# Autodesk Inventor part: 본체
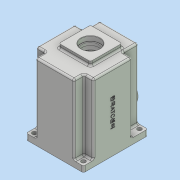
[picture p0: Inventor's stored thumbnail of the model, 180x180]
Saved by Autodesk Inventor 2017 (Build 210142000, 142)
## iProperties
Part Number: 본체
Material: 일반
Document SubType Name: Modeling
Designer: MRC
Density: 1 g/cm^3
Appearance: 기본값
Author: MRC
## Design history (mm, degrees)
sketch "스케치1"
  geometry: L1 (-33, -55)-(33, -55); L2 (33, -55)-(33, 55); L3 (33, 55)-(-33, 55); L4 (-33, 55)-(-33, -55); L5 (-33, -55)-(33, 55); L6 (33, -55)-(-33, 55); 1 further point
  constraints: 12 end point, 2 midpoint, 2 parallel, 1 horizontal, 1 perpendicular
  dimensions: "d0" = 66 distance of L3.end L2.end; "d1" = 110 distance of L2.end L1.end
extrude "돌출1" new body sketch "스케치1" distance "d2" = 130; taper "d3" = 0 deg
sketch "스케치2"
  geometry: L1 (-49, -38)-(49, -38); L2 (49, -38)-(49, 28); L3 (49, 28)-(-49, 28); L4 (-49, 28)-(-49, -38); L5 (-49, -38)-(49, 28); L6 (49, -38)-(-49, 28); L7 (-33, -55)-(33, -55) reference; 3 further points
  constraints: 12 end point, 3 midpoint, 2 parallel, 1 horizontal, 1 perpendicular, 1 vertical alignment
  dimensions: "d4" = 98 distance of L2.end L3.end; "d5" = 66 distance of L1.end L2.end; "d6" = 17 distance between parallel lines of L1 L7
extrude "돌출2" join sketch "스케치2" distance "d7" = 130; taper "d8" = 0 deg
sketch "스케치3"
  geometry: L1 (-49, -55)-(49, -55); L2 (49, -55)-(49, 55); L3 (49, 55)-(-49, 55); L4 (-49, 55)-(-49, -55); L5 (-49, -55)-(49, 55); L6 (49, -55)-(-49, 55); L7 (33, -55)-(-33, -55) reference; 3 further points
  constraints: 12 end point, 4 midpoint, 2 parallel, 1 horizontal, 1 perpendicular
  dimensions: "d9" = 98 distance of L3.end L2.end; "d10" = 110 distance of L2.end L1.end
extrude "돌출3" join sketch "스케치3" distance "d11" = 10; taper "d12" = 0 deg
node "작업 평면1"
sketch "스케치7"
  geometry: L1 (49, -55)-(-49, -55) reference; L2 (-26, 48)-(26, 48); L3 (-26, 48)-(-26, 31.729); L4 (26, 48)-(26, 31.729); A1 r 45 centre (0, -5) between (-26, 31.729) and (26, 31.729); 2 further points
  constraints: 6 end point, 2 point on circle, 2 vertical, 2 vertical alignment, 1 centre point, 1 horizontal, 1 midpoint
  dimensions: "d25" = 90 diameter of A1; "d26" = 50 distance from line of A1.centre L1; "d27" = 53 distance from line of A1.centre L2; "d28" = 52 distance of L2.start L2.end
extrude "돌출7" cut sketch "스케치7" distance "d29" = 9; taper "d30" = 0 deg
sketch "스케치13"
  geometry: L1 (-26, 48)-(26, 48) reference; L2 (-26, 31.729)-(-26, 48) reference; L3 (26, 48)-(26, 31.729) reference; L4 (-23, 30.143)-(-23, 45); L5 (-23, 45)-(23, 45); L6 (23, 45)-(23, 30.143); A1 r 45 centre (0, -5) between (-26, 31.729) and (26, 31.729) reference; A2 r 42 centre (0, -5) between (-23, 30.143) and (23, 30.143); 1 further point
  constraints: 6 end point, 2 point on circle, 1 centre point, 3 other
  dimensions: "d49" = 3 radial gap between concentric circles of A1 A2
extrude "돌출13" cut sketch "스케치13" distance "d50" = 112; taper "d51" = 0 deg
sketch "스케치14"
  geometry: L1 (49, -55)-(-49, -55) reference; C1 r 15 at (0, -25); C2 r 21 at (0, 6); 1 further point
  constraints: 2 centre point, 2 vertical alignment
  dimensions: "d52" = 30 diameter of C1; "d54" = 30 distance from line of C1.centre L1; "d55" = 42 diameter of C2; "d56" = 31 distance of C2.centre C1.centre
extrude "돌출14" join sketch "스케치14" distance "d57" = 7; taper "d58" = 0 deg
hole "구멍1" diameter "d61" = 19; stored, may be unused: countersink angle "d65" = 90 deg, drill point angle "d67" = 0 deg; dims "d62" = 6, "d63" = 22, "d64" = 7, "d66" = 10, "d68" = 10, "d69" = 10
sketch "스케치15"
  geometry: C1 r 17.5 at (0, 6); C2 r 11 at (0, -25) reference; A1 r 21 centre (0, 6) between (8.978, -12.984) and (-8.978, -12.984) reference; A2 r 15 centre (0, -25) between (-8.978, -12.984) and (8.978, -12.984) reference; 1 further point
  constraints: 1 centre point, 1 coincident
  dimensions: "d70" = 35 diameter of C1
extrude "돌출15" cut sketch "스케치15" distance "d71" = 10; taper "d72" = 0 deg
sketch "스케치16"
  geometry: L1 (-27, 33)-(27, 33); L2 (27, 33)-(27, -21); L3 (27, -21)-(-27, -21); L4 (-27, -21)-(-27, 33); L5 (-27, 33)-(27, -21); L6 (27, 33)-(-27, -21); A1 r 21 centre (0, 6) between (8.978, -12.984) and (-8.978, -12.984) reference; 4 further points
  constraints: 12 end point, 4 midpoint, 2 parallel, 1 coincident, 1 horizontal, 1 perpendicular, 1 vertical alignment
  dimensions: "d73" = 54 distance of L2.end L3.end; "d74" = 54 distance of L1.end L2.end
extrude "돌출16" join sketch "스케치16" distance "d75" = 7; taper "d76" = 0 deg
sketch "스케치17"
  geometry: L1 (27, 33)-(-27, 33) reference; L2 (-27, 33)-(-27, -21) reference; L3 (-27, -21)-(27, -21) reference; L4 (27, -21)-(27, 33) reference; C1 r 16 at (0, 6); 3 further points
  constraints: 2 midpoint, 1 centre point, 1 horizontal alignment, 1 vertical alignment
  dimensions: "d77" = 32 diameter of C1
extrude "돌출17" cut sketch "스케치17" distance "d78" = 8.3; taper "d79" = 0 deg
sketch "스케치18"
  geometry: C1 r 16 at (0, 0) reference; C2 r 14 at (0, 0); 1 further point
  constraints: 1 centre point, 1 coincident
  dimensions: "d80" = 28 diameter of C2
extrude "돌출18" cut sketch "스케치18" stored distance "d81" = 8.3; taper "d82" = 0 deg
sketch "스케치19"
  geometry: L1 (66, 0)-(0, 0) reference; L2 (-16, 130)-(82, 130) reference; C1 r 22.5 at (33, 90); 2 further points
  constraints: 1 centre point, 1 midpoint, 1 vertical alignment
  dimensions: "d83" = 45 diameter of C1; "d84" = 40 distance from line of C1.centre L2
extrude "돌출19" join sketch "스케치19" distance "d85" = 10; taper "d86" = 0 deg
sketch "스케치20"
  geometry: L1 (66, 0)-(0, 0) reference; C1 r 15 at (33, 41); C2 r 22.5 at (33, 90) reference; 2 further points
  constraints: 1 centre point, 1 midpoint, 1 vertical alignment
  dimensions: "d87" = 30 diameter of C1; "d88" = 49 distance of C1.centre C2.centre
extrude "돌출20" join sketch "스케치20" distance "d89" = 5; taper "d90" = 0 deg
sketch "스케치21"
  geometry: C1 r 10 at (0, 0); C2 r 15 at (0, 0) reference; 1 further point
  constraints: 1 centre point, 1 concentric
  dimensions: "d91" = 20 diameter of C1
extrude "돌출21" cut sketch "스케치21" stored distance "d92" = 5; taper "d93" = 0 deg
sketch "스케치22"
  geometry: C1 r 15 at (23, 80); C2 r 10 at (23, 80) reference; 1 further point
  constraints: 1 centre point, 1 concentric
  dimensions: "d94" = 30 diameter of C1
extrude "돌출22" cut sketch "스케치22" distance "d95" = 5; taper "d96" = 0 deg
hole "구멍2" diameter "d99" = 33.376; stored, may be unused: countersink angle "d103" = 90 deg, drill point angle "d105" = 118 deg; dims "d97" = 10, "d98" = 10, "d100" = 30, "d101" = 35, "d102" = 10, "d104" = 77.3
sketch "스케치23"
  geometry: L1 (49, 55)-(-49, 55) reference; L2 (-49, 55)-(-49, -55) reference; L3 (49, -55)-(49, 55) reference; L4 (49, -55)-(-49, -55) reference; C1 r 3.5 at (-42, 48); C2 r 3.5 at (-42, -48); C3 r 3.5 at (42, -48); C4 r 3.5 at (42, 48); 1 further point
  constraints: 4 centre point
  dimensions: "d106" = 7 diameter of C1; "d107" = 7 distance from line of C1.centre L1; "d108" = 7 distance from line of C1.centre L2; "d109" = 7 diameter of C2; "d110" = 7 diameter of C3; "d111" = 7 diameter of C4; "d113" = 84 distance of C4.centre C1.centre; "d114" = 96 distance of C3.centre C4.centre; "d115" = 96 distance of C2.centre C1.centre; "d116" = 7 distance from line of C2.centre L2; "d117" = 7 distance from line of L3 C3.centre; "d118" = 7 distance from line of L4 C3.centre
extrude "돌출23" cut sketch "스케치23" stored distance "d119" = 5; taper "d120" = 0 deg
sketch "스케치24"
  geometry: L1 (49, -55)-(-49, -55) reference; L2 (23, 45)-(23, 30.143) reference; L3 (-23, 45)-(23, 45) reference; L4 (-23, 30.143)-(-23, 45) reference; L5 (36, -1)-(41.809, -1); L6 (36, -9)-(41.809, -9); L7 (-36, -1)-(-41.809, -1); L8 (-36, -9)-(-41.809, -9); A1 r 36 centre (0, -5) between (36, -5) and (-36, -5); A2 r 4 centre (36, -5) between (36, -1) and (36, -9); A3 r 4 centre (-36, -5) between (-36, -9) and (-36, -1); A4 r 21 centre (0, 6) between (8.978, -12.984) and (-8.978, -12.984) reference; A5 r 15 centre (0, -25) between (-8.978, -12.984) and (8.978, -12.984) reference; A6 r 42 centre (0, -5) between (-23, 30.143) and (23, 30.143) reference; 1 further point
  constraints: 10 point on circle, 8 end point, 4 horizontal, 4 tangent, 3 centre point, 1 vertical alignment
  dimensions: "d121" = 72 diameter of A1; "d122" = 50 distance from line of A1.centre L1; "d123" = 8 diameter of A2; "d124" = 8 diameter of A3; "d125" = 11 vertical distance of A1.start A4.centre; "d126" = 11 vertical distance of A1.end A4.centre
extrude "돌출24" join sketch "스케치24" stored distance "d127" = 5; taper "d128" = 0 deg
fillet "모깎기1" dims "d129" = 3
fillet "모깎기2" dims "d130" = 3
sketch "스케치25"
  geometry: L1 (23, 45)-(23, 30.143) reference; L2 (38.367, -1)-(36, -1) reference; L3 (36, -9)-(38.367, -9) reference; L4 (-38.367, -9)-(-36, -9) reference; L5 (-36, -1)-(-38.367, -1) reference; L6 (-23, 30.143)-(-23, 45) reference; L7 (-23, 45)-(23, 45) reference; L8 (-26, 48)-(26, 48) reference; L9 (-26, 31.729)-(-26, 48) reference; L10 (26, 48)-(26, 31.729) reference; A1 r 42 centre (0, -5) between (41.318, 2.538) and (23, 30.143) reference; A2 r 3 centre (38.367, 2) between (38.367, -1) and (41.318, 2.538) reference; A3 r 4 centre (36, -5) between (36, -1) and (36, -9) reference; A4 r 3 centre (38.367, -12) between (41.318, -12.538) and (38.367, -9) reference; A5 r 42 centre (0, -5) between (-41.318, -12.538) and (41.318, -12.538) reference; A6 r 3 centre (-38.367, -12) between (-38.367, -9) and (-41.318, -12.538) reference; A7 r 4 centre (-36, -5) between (-36, -9) and (-36, -1) reference; A8 r 3 centre (-38.367, 2) between (-41.318, 2.538) and (-38.367, -1) reference; A9 r 42 centre (0, -5) between (-23, 30.143) and (-41.318, 2.538) reference; A10 r 45 centre (0, -5) between (-26, 31.729) and (26, 31.729) reference; 3 further points
  constraints: 2 coincident
hole "구멍3" sketch "스케치25" at (-36, -5), (36, -5) diameter "d131" = 3.242; stored, may be unused: countersink angle "d135" = 90 deg, drill point angle "d137" = 118 deg; dims "d132" = 7, "d133" = 35, "d134" = 10, "d136" = 9
fillet "모깎기3" dims "d138" = 3
fillet "모깎기4" dims "d139" = 3
fillet "모깎기5" dims "d140" = 3
fillet "모깎기6" dims "d141" = 3
fillet "모깎기7" dims "d142" = 3
fillet "모깎기8" dims "d143" = 3
fillet "모깎기9" dims "d144" = 6
fillet "모깎기10" dims "d145" = 3
fillet "모깎기11" dims "d146" = 3
fillet "모깎기12" dims "d147" = 3
chamfer "모따기1" distance "d148" = 1; stored, may be unused: second distance "d149" = 2, angle "d150" = 45 deg
fillet "모깎기13" dims "d151" = 3
chamfer "모따기2" distance "d152" = 0.8; stored, may be unused: second distance "d153" = 2, angle "d154" = 30 deg
fillet "모깎기14" dims "d155" = 0.3
sketch "스케치26"
  geometry: L1 (-130, 107)-(-130, 86) reference; L2 (-13, 83)-(-127, 83) reference; 2 further points
  constraints: 1 other
  dimensions: "d156" = 65 distance from line of point (-65, 50) L1; "d157" = 33 distance from line of point (-65, 50) L2
feature "엠보싱1" sketch "스케치26" dims "d158" = 0.5, "d159" = 0
fillet "모깎기15" dims "d160" = 3
fillet "모깎기16" dims "d161" = 3
fillet "모깎기17" dims "d162" = 0.3
fillet "모깎기18" dims "d163" = 0.3
node "솔리드1"
node "투영된 루프5"
node "투영된 루프6"
node "투영된 루프7"
node "투영된 루프8"
node "투영된 루프9"
node "투영된 루프10"
node "투영된 루프11"
